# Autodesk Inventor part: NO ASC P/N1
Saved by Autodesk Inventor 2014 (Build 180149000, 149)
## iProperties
Shininess: 64.0
Length Units: 11272
Angle Units: 11279
Time Units: 11290
Mass Units: 11286
Length Display Precision: 3
Angle Display Precision: 2
Company: Autodesk, Inc.
Created: 2001-12
Part Number: NO ASC P/N1
Material: Steel, Mild
Description: FITTING; MC-G2-S
Document SubType Name: Modeling
Designer: Autodesk, Inc.
Density: 7.75 g/cm^3
Appearance: Yellow Zinc
Density: 7.75
Volumn: 1.1899929784618444
Area: 7.049002142317107
PropertySet Name: Model Information
Control State: 0
Master: False
Checked Out: False
Last Check In By: JT
Last Check In Date: 2003-06-20
Title: FITTING; MC-G2-S
Author: Autodesk, Inc.
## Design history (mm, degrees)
sketch "Sketch1"
  geometry: L1 (5.556, -3.208)-(0, -6.416); L2 (0, -6.416)-(-5.556, -3.208); L3 (-5.556, -3.208)-(-5.556, 3.208); L4 (-5.556, 3.208)-(0, 6.416); L5 (0, 6.416)-(5.556, 3.208); L6 (5.556, 3.208)-(5.556, -3.208); C1 r 5.556 at (0, 0); 2 further points
  constraints: 12 end point, 2 coincident, 1 centre point, 1 tangent, 1 vertical, 11 other
  dimensions: "Hex_Flats" = 11.1125 diameter of C1
extrude "Extrusion1" new body sketch "Sketch1" taper "d2" = 0 deg; distance "Hex_Thickness" = 7.366 (= Total_Length - Thread_Length)
sketch "Sketch2"
  geometry: L1 (0, 6.416)-(5.556, 3.208) reference; L2 (-5.556, -3.208)-(-5.556, 3.208) reference; L3 (-5.556, 3.208)-(5.556, -3.208); L4 (0, -6.416)-(0, 6.416); C1 r 3.969 at (0, 0)
  constraints: 4 end point, 2 parallel, 1 centre point, 1 midpoint
  dimensions: "Thread_Size" = 7.9375 diameter of C1
extrude "Extrusion2" join sketch "Sketch2" taper "d5" = 0 deg; distance "Thread_Length" = 7.62
sketch "Sketch3"
  geometry: L1 (6.416, 0)-(6.416, 7.366) reference; L2 (-6.416, 0)-(-6.416, 7.366) reference; L3 (6.416, 7.366)-(-6.416, 7.366); L4 (-6.416, 0)-(6.416, 0); L5 (-6.416, 7.136)-(-5.556, 7.366); L6 (-6.416, 0.23)-(-5.556, 0); L7 (0, 7.366)-(0, 0)
  constraints: 10 end point, 4 point on line, 2 midpoint, 1 equal length, 1 parallel, 1 perpendicular, 1 vertical alignment
  dimensions: "d15" = 15 deg angle of L4 L6; "d16" = 11.1125 diameter of L6.end L7 (= Hex_Flats)
revolve "Revolution1" sketch "Sketch3" stored, may be unused: angle "d8" = 90 deg
chamfer "Chamfer1" distance "d9" = 0.79375; stored, may be unused: second distance "d10" = 0.79375, angle "d17" = 45 deg
sketch "Sketch4" dims "Oring_Thickness" = 1.778
  geometry: L1 (-3.969, 7.366)-(-3.969, 14.192) reference; L2 (0, 6.001)-(0, 15.558) reference; 1 further point
  constraints: 1 point on line, 1 vertical alignment, 2 other
revolve "Revolution2" sketch "Sketch4" stored, may be unused: angle "d12" = 90 deg
thread "Thread1" dims "d13" = 25.4, "d14" = 0
body "Solid1"
other parameters: "Total_Length" = 14.986 [user parameter; used in 1 equation term]
